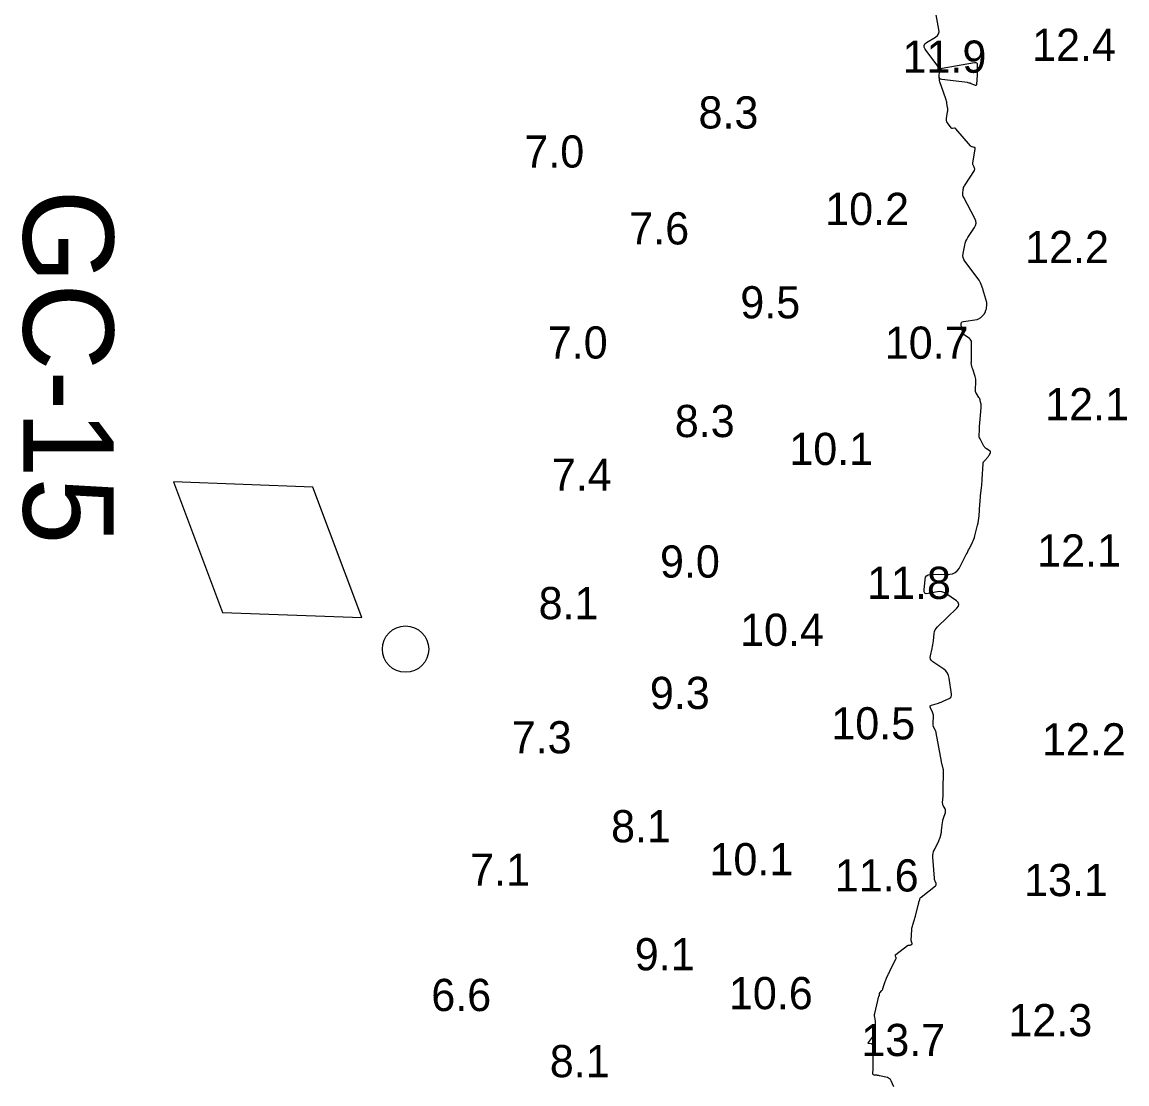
# Model space of a CAD drawing. Extents: x 815352 to 820877, y 582403 to 597439.
# Drawn here: x 820396.5 to 820568.1, y 590177.1 to 590342 of the extents above; entities that cross this region are included whole.
import ezdxf

# ---------------------------------------------------------------- set-up
doc = ezdxf.new("R2010")
doc.units = 0
for name, color, linetype in [('V-CHAN-NAID', 7, 'Continuous'), ('V-CONT-EL12', 7, 'Continuous'), ('V-TOPO-SOUN', 7, 'Continuous')]:
    doc.layers.add(name, color=color, linetype=linetype)

msp = doc.modelspace()

# ---------------------------------------------------------------- linework, layer by layer
at = {"layer": 'V-CHAN-NAID'}
msp.add_lwpolyline([(820449.24, 590249.56), (820441.65, 590269.82), (820420.04, 590270.62), (820427.62, 590250.36)], close=True, dxfattribs=at)
msp.add_circle((820456.05, 590244.65), 3.6, dxfattribs=at)
at = {"layer": 'V-CONT-EL12'}
msp.add_lwpolyline([(820531.86, 590176.66), (820531.44, 590177.63), (820531.34, 590177.81), (820531.21, 590177.94), (820531.05, 590178.04), (820530.87, 590178.11), (820529.62, 590178.39), (820529.52, 590178.42), (820529.42, 590178.43), (820529.32, 590178.45), (820529.22, 590178.46), (820528.81, 590178.51), (820528.73, 590178.54), (820528.67, 590178.58), (820528.63, 590178.65), (820528.62, 590178.74), (820528.66, 590179.43), (820528.67, 590179.58), (820528.67, 590179.73), (820528.67, 590179.88), (820528.67, 590180.03), (820528.58, 590183.14), (820528.57, 590183.22), (820528.53, 590183.28), (820528.47, 590183.32), (820528.39, 590183.34), (820528.02, 590183.38), (820527.94, 590183.4), (820527.9, 590183.44), (820527.9, 590183.49), (820527.94, 590183.56), (820528.53, 590184.37), (820528.64, 590184.53), (820528.72, 590184.71), (820528.79, 590184.89), (820528.83, 590185.08), (820529.02, 590186.24), (820529.04, 590186.39), (820529.04, 590186.55), (820529.03, 590186.7), (820529.01, 590186.86), (820528.89, 590187.47), (820528.86, 590187.62), (820528.86, 590187.77), (820528.87, 590187.93), (820528.9, 590188.08), (820529.55, 590190.77), (820529.56, 590190.78), (820529.57, 590190.8), (820529.58, 590190.81), (820529.59, 590190.83), (820529.64, 590190.88), (820529.65, 590190.89), (820529.66, 590190.91), (820529.66, 590190.92), (820529.66, 590190.94), (820529.65, 590191.13), (820529.65, 590191.16), (820529.65, 590191.2), (820529.67, 590191.23), (820529.69, 590191.26), (820530, 590191.61), (820530.06, 590191.69), (820530.1, 590191.76), (820530.15, 590191.84), (820530.18, 590191.93), (820530.54, 590193.01), (820530.59, 590193.15), (820530.64, 590193.29), (820530.7, 590193.42), (820530.75, 590193.56), (820531, 590194.1), (820531.06, 590194.23), (820531.12, 590194.37), (820531.18, 590194.5), (820531.25, 590194.63), (820532.19, 590196.56), (820532.21, 590196.62), (820532.22, 590196.68), (820532.22, 590196.74), (820532.2, 590196.8), (820532.12, 590197.04), (820532.11, 590197.1), (820532.12, 590197.16), (820532.14, 590197.2), (820532.19, 590197.25), (820534.01, 590198.61), (820534.04, 590198.64), (820534.08, 590198.65), (820534.12, 590198.66), (820534.16, 590198.67), (820534.34, 590198.68), (820534.38, 590198.69), (820534.42, 590198.7), (820534.46, 590198.71), (820534.5, 590198.73), (820534.64, 590198.83), (820534.67, 590198.85), (820534.69, 590198.88), (820534.7, 590198.92), (820534.69, 590198.95), (820534.61, 590199.19), (820534.6, 590199.24), (820534.59, 590199.3), (820534.58, 590199.35), (820534.58, 590199.4), (820534.67, 590201.12), (820534.68, 590201.3), (820534.71, 590201.48), (820534.75, 590201.65), (820534.8, 590201.82), (820535.03, 590202.5), (820535.08, 590202.67), (820535.14, 590202.85), (820535.19, 590203.02), (820535.23, 590203.19), (820535.66, 590204.9), (820535.69, 590205.01), (820535.72, 590205.12), (820535.74, 590205.23), (820535.77, 590205.34), (820535.88, 590205.79), (820535.92, 590205.89), (820535.97, 590205.99), (820536.03, 590206.08), (820536.12, 590206.15), (820538.33, 590207.88), (820538.41, 590207.96), (820538.45, 590208.04), (820538.45, 590208.13), (820538.43, 590208.23), (820538.26, 590208.64), (820538.22, 590208.74), (820538.19, 590208.85), (820538.17, 590208.96), (820538.16, 590209.07), (820537.93, 590212.34), (820537.93, 590212.64), (820537.97, 590212.93), (820538.04, 590213.22), (820538.16, 590213.5), (820538.85, 590214.89), (820538.9, 590215.01), (820538.96, 590215.14), (820539, 590215.27), (820539.04, 590215.41), (820539.19, 590215.95), (820539.22, 590216.08), (820539.25, 590216.22), (820539.28, 590216.36), (820539.29, 590216.49), (820539.43, 590217.75), (820539.45, 590217.91), (820539.48, 590218.08), (820539.52, 590218.24), (820539.57, 590218.4), (820539.87, 590219.27), (820539.89, 590219.31), (820539.9, 590219.36), (820539.9, 590219.41), (820539.9, 590219.46), (820539.88, 590219.65), (820539.88, 590219.7), (820539.87, 590219.75), (820539.85, 590219.79), (820539.83, 590219.84), (820539.54, 590220.38), (820539.49, 590220.49), (820539.46, 590220.6), (820539.44, 590220.72), (820539.44, 590220.84), (820539.52, 590221.82), (820539.53, 590222.02), (820539.54, 590222.23), (820539.55, 590222.43), (820539.55, 590222.64), (820539.56, 590225.8), (820539.56, 590225.92), (820539.54, 590226.04), (820539.52, 590226.15), (820539.49, 590226.27), (820539.36, 590226.72), (820539.33, 590226.84), (820539.31, 590226.95), (820539.28, 590227.07), (820539.26, 590227.18), (820538.45, 590231.63), (820538.42, 590231.75), (820538.38, 590231.87), (820538.34, 590231.99), (820538.28, 590232.1), (820537.98, 590232.7), (820537.96, 590232.74), (820537.95, 590232.78), (820537.94, 590232.83), (820537.95, 590232.87), (820537.97, 590233.05), (820537.98, 590233.1), (820537.98, 590233.14), (820537.99, 590233.19), (820537.99, 590233.23), (820538.02, 590234.21), (820538.02, 590234.38), (820537.99, 590234.56), (820537.94, 590234.72), (820537.88, 590234.88), (820537.54, 590235.55), (820537.49, 590235.7), (820537.51, 590235.82), (820537.59, 590235.91), (820537.73, 590235.97), (820538.81, 590236.28), (820539.02, 590236.34), (820539.24, 590236.42), (820539.44, 590236.5), (820539.65, 590236.6), (820540.46, 590236.99), (820540.64, 590237.11), (820540.75, 590237.25), (820540.81, 590237.43), (820540.81, 590237.64), (820540.47, 590240.15), (820540.37, 590240.57), (820540.2, 590240.94), (820539.95, 590241.26), (820539.62, 590241.53), (820537.92, 590242.7), (820537.71, 590242.88), (820537.58, 590243.09), (820537.53, 590243.33), (820537.56, 590243.6), (820537.82, 590244.76), (820537.88, 590245.04), (820537.93, 590245.33), (820537.98, 590245.62), (820538.01, 590245.92), (820538.14, 590247.1), (820538.2, 590247.38), (820538.3, 590247.65), (820538.45, 590247.88), (820538.64, 590248.1), (820541.66, 590251), (820541.9, 590251.31), (820541.97, 590251.6), (820541.86, 590251.88), (820541.57, 590252.14), (820539.92, 590253.28), (820539.62, 590253.45), (820539.3, 590253.55), (820538.97, 590253.59), (820538.62, 590253.55), (820537.21, 590253.28), (820536.91, 590253.26), (820536.7, 590253.35), (820536.59, 590253.55), (820536.57, 590253.86), (820536.71, 590255.47), (820536.78, 590255.81), (820536.95, 590256.06), (820537.2, 590256.21), (820537.55, 590256.26), (820540.54, 590256.31), (820541, 590256.37), (820541.4, 590256.53), (820541.72, 590256.81), (820541.99, 590257.19), (820543.11, 590259.34), (820543.23, 590259.58), (820543.35, 590259.82), (820543.47, 590260.06), (820543.59, 590260.3), (820544.07, 590261.25), (820544.18, 590261.49), (820544.28, 590261.74), (820544.37, 590261.99), (820544.44, 590262.25), (820544.88, 590263.9), (820544.97, 590264.26), (820545.03, 590264.63), (820545.08, 590264.99), (820545.12, 590265.37), (820545.23, 590267.19), (820545.25, 590267.51), (820545.28, 590267.83), (820545.31, 590268.15), (820545.34, 590268.47), (820545.49, 590269.75), (820545.52, 590270.07), (820545.55, 590270.39), (820545.58, 590270.71), (820545.6, 590271.03), (820545.74, 590273.44), (820545.76, 590273.58), (820545.81, 590273.72), (820545.88, 590273.84), (820545.97, 590273.96), (820546.46, 590274.48), (820546.52, 590274.55), (820546.58, 590274.62), (820546.63, 590274.7), (820546.68, 590274.79), (820546.86, 590275.12), (820546.9, 590275.2), (820546.89, 590275.27), (820546.86, 590275.34), (820546.8, 590275.4), (820546.23, 590275.77), (820546.12, 590275.86), (820546.02, 590275.96), (820545.93, 590276.07), (820545.85, 590276.19), (820545.26, 590277.3), (820545.19, 590277.45), (820545.14, 590277.6), (820545.12, 590277.76), (820545.11, 590277.92), (820545.15, 590278.58), (820545.16, 590278.75), (820545.17, 590278.91), (820545.18, 590279.08), (820545.19, 590279.24), (820545.44, 590282.12), (820545.44, 590282.26), (820545.44, 590282.4), (820545.43, 590282.54), (820545.4, 590282.68), (820545.29, 590283.24), (820545.26, 590283.37), (820545.21, 590283.5), (820545.15, 590283.63), (820545.08, 590283.75), (820544.69, 590284.35), (820544.61, 590284.49), (820544.56, 590284.64), (820544.53, 590284.79), (820544.53, 590284.95), (820544.61, 590286.1), (820544.61, 590286.33), (820544.59, 590286.56), (820544.55, 590286.79), (820544.49, 590287.01), (820544.11, 590288.15), (820544.08, 590288.25), (820544.05, 590288.35), (820544.03, 590288.45), (820544, 590288.55), (820543.87, 590289.14), (820543.87, 590289.15), (820543.87, 590289.16), (820543.88, 590289.17), (820543.89, 590289.18), (820543.92, 590289.21), (820543.93, 590289.22), (820543.93, 590289.23), (820543.93, 590289.24), (820543.93, 590289.25), (820543.92, 590292.29), (820543.9, 590292.48), (820543.84, 590292.64), (820543.74, 590292.79), (820543.6, 590292.91), (820542.95, 590293.37), (820542.8, 590293.49), (820542.69, 590293.63), (820542.6, 590293.8), (820542.54, 590293.98), (820542.32, 590294.99), (820542.31, 590295.2), (820542.36, 590295.36), (820542.49, 590295.47), (820542.69, 590295.53), (820544.78, 590295.87), (820544.93, 590295.9), (820545.07, 590295.96), (820545.19, 590296.03), (820545.31, 590296.13), (820545.85, 590296.64), (820545.91, 590296.71), (820545.97, 590296.78), (820546.01, 590296.86), (820546.05, 590296.95), (820546.17, 590297.3), (820546.2, 590297.39), (820546.23, 590297.48), (820546.25, 590297.57), (820546.26, 590297.67), (820546.31, 590298.09), (820546.32, 590298.19), (820546.32, 590298.29), (820546.3, 590298.39), (820546.28, 590298.49), (820545.68, 590300.56), (820545.67, 590300.61), (820545.66, 590300.65), (820545.64, 590300.69), (820545.63, 590300.73), (820545.57, 590300.89), (820545.56, 590300.93), (820545.55, 590300.97), (820545.53, 590301.01), (820545.52, 590301.04), (820545.32, 590301.56), (820545.27, 590301.66), (820545.23, 590301.75), (820545.17, 590301.84), (820545.11, 590301.93), (820542.88, 590304.9), (820542.71, 590305.17), (820542.61, 590305.46), (820542.58, 590305.76), (820542.61, 590306.08), (820542.87, 590307.37), (820542.95, 590307.69), (820543.06, 590308), (820543.2, 590308.29), (820543.36, 590308.57), (820544.38, 590310.11), (820544.56, 590310.46), (820544.63, 590310.82), (820544.59, 590311.18), (820544.45, 590311.55), (820542.71, 590314.8), (820542.65, 590314.94), (820542.6, 590315.09), (820542.58, 590315.24), (820542.58, 590315.4), (820542.63, 590316.04), (820542.66, 590316.2), (820542.7, 590316.35), (820542.76, 590316.49), (820542.83, 590316.63), (820544.37, 590319.01), (820544.41, 590319.09), (820544.43, 590319.18), (820544.42, 590319.27), (820544.39, 590319.37), (820544.21, 590319.74), (820544.17, 590319.84), (820544.15, 590319.93), (820544.14, 590320.03), (820544.15, 590320.14), (820544.5, 590322.36), (820544.5, 590322.43), (820544.48, 590322.49), (820544.43, 590322.54), (820544.36, 590322.57), (820544.04, 590322.66), (820543.96, 590322.68), (820543.89, 590322.72), (820543.83, 590322.77), (820543.77, 590322.83), (820541.5, 590325.48), (820541.45, 590325.53), (820541.4, 590325.55), (820541.34, 590325.57), (820541.27, 590325.56), (820541, 590325.51), (820540.93, 590325.51), (820540.87, 590325.52), (820540.82, 590325.55), (820540.78, 590325.6), (820540.2, 590326.4), (820540.11, 590326.56), (820540.06, 590326.73), (820540.03, 590326.9), (820540.05, 590327.08), (820540.22, 590328.09), (820540.24, 590328.26), (820540.25, 590328.43), (820540.24, 590328.6), (820540.22, 590328.77), (820540.1, 590329.44), (820540.07, 590329.61), (820540.03, 590329.77), (820539.98, 590329.94), (820539.93, 590330.1), (820539.03, 590332.76), (820538.98, 590332.96), (820538.94, 590333.17), (820538.92, 590333.37), (820538.92, 590333.58), (820538.95, 590334.41), (820538.94, 590334.62), (820538.9, 590334.81), (820538.83, 590334.99), (820538.72, 590335.17), (820536.75, 590337.83), (820536.59, 590338.14), (820536.57, 590338.41), (820536.69, 590338.66), (820536.96, 590338.88), (820538.33, 590339.7), (820538.62, 590339.93), (820538.8, 590340.21), (820538.88, 590340.53), (820538.86, 590340.9), (820538.42, 590343.15)], dxfattribs=at)
msp.add_lwpolyline([(820544.8, 590334.4), (820544.8, 590334.19), (820544.79, 590333.99), (820544.78, 590333.78), (820544.71, 590332.41), (820544.69, 590332.28), (820544.63, 590332.21), (820544.54, 590332.19), (820544.42, 590332.23), (820543.86, 590332.47), (820543.72, 590332.53), (820543.58, 590332.57), (820543.43, 590332.61), (820543.29, 590332.63), (820539.31, 590333.11), (820539.13, 590333.16), (820539.01, 590333.25), (820538.94, 590333.39), (820538.92, 590333.58), (820538.95, 590334.41), (820538.99, 590334.6), (820539.07, 590334.74), (820539.2, 590334.84), (820539.38, 590334.9), (820544.4, 590335.78), (820544.58, 590335.78), (820544.71, 590335.73), (820544.78, 590335.61), (820544.81, 590335.44), (820544.8, 590334.61)], close=True, dxfattribs=at)

# ---------------------------------------------------------------- texts
at = {"layer": 'V-CHAN-NAID'}
msp.add_text('GC-15', height=14, rotation=270, dxfattribs=at).set_placement((820396.71, 590316.04))
at = {"layer": 'V-TOPO-SOUN'}
for s, p in [('12.4 ', (820553.33, 590336.01)), ('11.9 ', (820533.22, 590334.17)), ('8.3', (820501.54, 590325.51)), ('7.0', (820474.5, 590319.44)), ('10.2 ', (820521.21, 590310.52)), ('7.6', (820490.79, 590307.5)), ('12.2 ', (820552.25, 590304.61)), ('9.5', (820508.03, 590296.02)), ('7.0', (820478.14, 590289.78)), ('10.7 ', (820530.46, 590289.75)), ('12.1 ', (820555.37, 590280.2)), ('8.3', (820497.86, 590277.58)), ('10.1 ', (820515.64, 590273.25)), ('7.4', (820478.77, 590269.24)), ('12.1 ', (820554.12, 590257.47)), ('9.0', (820495.56, 590255.76)), ('11.8 ', (820527.71, 590252.45)), ('8.1', (820476.71, 590249.3)), ('10.4 ', (820507.99, 590245.16)), ('9.3', (820493.99, 590235.35)), ('10.5 ', (820522.16, 590230.63)), ('7.3', (820472.54, 590228.46)), ('12.2 ', (820554.87, 590228.14)), ('8.1', (820487.96, 590214.65)), ('10.1 ', (820503.24, 590209.53)), ('7.1', (820466.08, 590207.89)), ('11.6 ', (820522.7, 590207.01)), ('13.1 ', (820552.09, 590206.29)), ('9.1', (820491.64, 590194.77)), ('6.6', (820460.05, 590188.44)), ('10.6 ', (820506.26, 590188.73)), ('12.3 ', (820549.65, 590184.53)), ('13.7 ', (820526.82, 590181.45)), ('8.1', (820478.45, 590178.17))]:
    msp.add_text(s, height=5, dxfattribs=at).set_placement(p)

doc.saveas('drawing.dxf')
